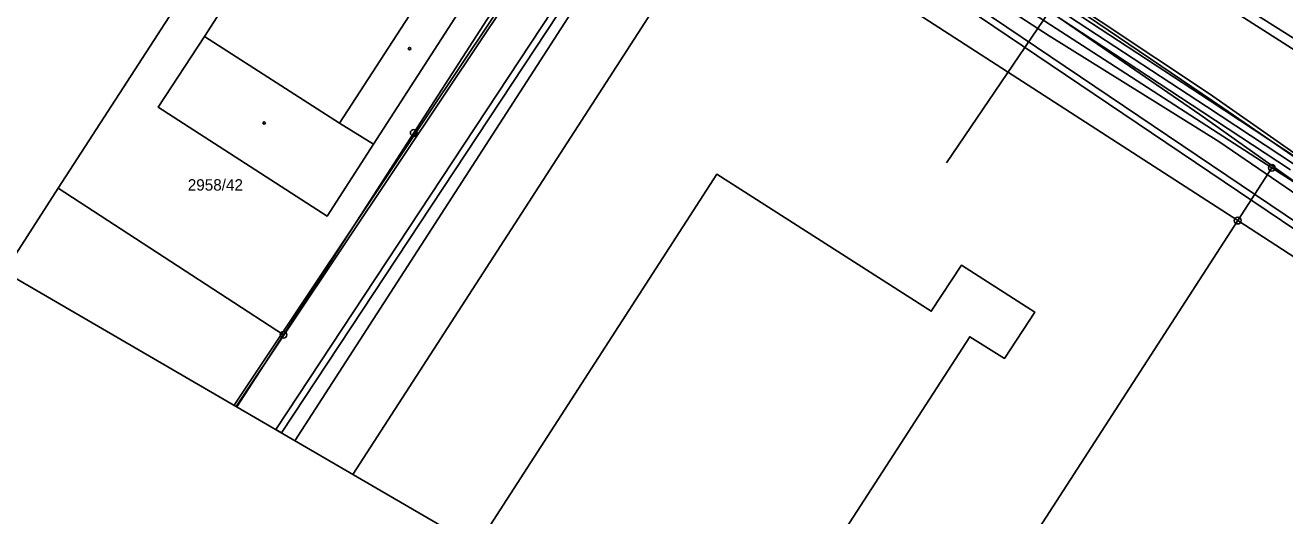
# Model space of a CAD drawing. Extents: x -621168 to -620292, y -1122748 to -1122069.
# Drawn here: x -620762.3 to -620574.7, y -1122596.3 to -1122523.2 of the extents above; entities that cross this region are included whole.
import ezdxf

# ---------------------------------------------------------------- set-up
doc = ezdxf.new("R2010")
doc.units = 0
for name, color, linetype in [('CETIN', 7, 'Continuous'), ('GasNet', 7, 'Continuous'), ('Hranice parcel', 7, 'Continuous'), ('itself', 7, 'Continuous'), ('Parcelní čísla', 7, 'Continuous'), ('Rámečky-tisk', 7, 'Continuous'), ('VAS stoka', 7, 'Continuous'), ('VAS vodovod', 7, 'Continuous'), ('Vnitřní kresba', 7, 'Continuous'), ('Věcná břemena k části', 7, 'Continuous'), ('Značky bodu BP', 7, 'Continuous'), ('Značky budov', 7, 'Continuous')]:
    doc.layers.add(name, color=color, linetype=linetype)

msp = doc.modelspace()

# ---------------------------------------------------------------- linework, layer by layer
at = {"layer": 'CETIN'}
msp.add_lwpolyline([(-620646.43, -1122495.05), (-620612.92, -1122515.84), (-620612.23, -1122516.26), (-620607.1, -1122519.79), (-620583.87, -1122535.51), (-620565.48, -1122548.17), (-620561.56, -1122551.58), (-620557.36, -1122556.05), (-620552.9, -1122562.72), (-620546.13, -1122574.35), (-620544.03, -1122578.53)], dxfattribs=at)
at = {"layer": 'GasNet'}
msp.add_lwpolyline([(-620782.63, -1122409.86), (-620782.01, -1122410.24), (-620780.25, -1122411.07), (-620777.02, -1122412.94), (-620768.84, -1122416.49), (-620765.93, -1122417.88), (-620758.63, -1122422.59), (-620737.62, -1122436.24), (-620727.26, -1122442.97), (-620706.73, -1122456.7), (-620700.22, -1122460.96), (-620682.51, -1122472.52), (-620658.5, -1122488), (-620649.67, -1122493.31), (-620649.45, -1122493.45), (-620648.52, -1122494.04), (-620647.09, -1122494.92), (-620646.9, -1122495.04), (-620639.06, -1122500.54), (-620610.88, -1122519.2), (-620586.31, -1122535.34), (-620573.22, -1122543.96)], dxfattribs=at)
at = {"layer": 'Hranice parcel'}
for p, q in [((-620722.11, -1122585.09), (-620660.74, -1122490.09)), ((-620660.74, -1122490.09), (-620576.58, -1122544.45)), ((-620581.67, -1122552.32), (-620576.58, -1122544.45)), ((-620765.39, -1122559.92), (-620757.37, -1122547.51)), ((-620757.37, -1122547.51), (-620723.81, -1122569.32)), ((-620581.67, -1122552.32), (-620635.41, -1122635.51))]:
    msp.add_line(p, q, dxfattribs=at)
for points in [[(-620557.45, -1122536.96), (-620684.91, -1122455.63), (-620825.92, -1122365.89)], [(-620757.37, -1122547.51), (-620738.01, -1122517.55), (-620702.74, -1122462.95)], [(-620669.14, -1122484.66), (-620704.41, -1122539.26), (-620723.81, -1122569.32)], [(-620702.63, -1122495.93), (-620709.28, -1122506.15), (-620699.07, -1122512.52), (-620694.2, -1122515.81), (-620710.42, -1122540.95), (-620717.32, -1122551.67), (-620742.46, -1122535.43), (-620735.6, -1122524.88), (-620719.36, -1122499.62), (-620712.73, -1122489.39)], [(-620581.67, -1122552.32), (-620657.43, -1122503.38), (-620713.46, -1122590.12)], [(-620576.58, -1122544.45), (-620572.54, -1122547.06), (-620562.8, -1122553.35)], [(-620656.31, -1122623.35), (-620621.58, -1122569.6), (-620616.39, -1122572.84), (-620611.91, -1122565.95), (-620622.82, -1122558.97), (-620627.31, -1122565.82), (-620652.1, -1122549.99), (-620659.27, -1122545.41), (-620695.05, -1122600.83)], [(-620581.67, -1122552.32), (-620562.67, -1122564.59), (-620546.5, -1122612)], [(-620723.81, -1122569.32), (-620730.74, -1122580.07)]]:
    msp.add_lwpolyline(points, dxfattribs=at)
at = {"layer": 'itself'}
msp.add_lwpolyline([(-620570.67, -1122549.95), (-620584.48, -1122540.56), (-620609.76, -1122524.78), (-620613.13, -1122522.62), (-620616.25, -1122520.59), (-620644.13, -1122502.42), (-620648.74, -1122499.33), (-620649.95, -1122498.54), (-620675.91, -1122481.07), (-620699.14, -1122464.9), (-620705.51, -1122460.51), (-620711.67, -1122456.57), (-620715.75, -1122454.11), (-620716.79, -1122453.45), (-620721.67, -1122450.84), (-620745.77, -1122435.49), (-620776.46, -1122415.3)], dxfattribs=at)
at = {"layer": 'Rámečky-tisk'}
msp.add_lwpolyline([(-621018.54, -1122069.17), (-621167.83, -1122325.92), (-620441.66, -1122748.16)], dxfattribs=at)
at = {"layer": 'VAS stoka'}
for points in [[(-620781.72, -1122408.87), (-620776.69, -1122412.14), (-620774.2, -1122412.02), (-620772.21, -1122412.95), (-620766.77, -1122415.95), (-620758.11, -1122421.89), (-620737.16, -1122435.39), (-620726.71, -1122442.22), (-620705.9, -1122455.54), (-620681.71, -1122471.08), (-620665.23, -1122481.83), (-620655.61, -1122488.12), (-620638.12, -1122499.53), (-620609.99, -1122517.38), (-620585.88, -1122533.44), (-620564.23, -1122548.6), (-620546.83, -1122572.05), (-620541.25, -1122582.33), (-620541.87, -1122584.42), (-620543.53, -1122584.85), (-620544.25, -1122585.03)], [(-620730.84, -1122580.01), (-620699.26, -1122532.75), (-620665.23, -1122481.83)]]:
    msp.add_lwpolyline(points, dxfattribs=at)
at = {"layer": 'VAS vodovod'}
msp.add_line((-620609.72, -1122521.13), (-620625.07, -1122543.73), dxfattribs=at)
for points in [[(-620783.05, -1122410.36), (-620779.49, -1122412.44), (-620776.82, -1122413.57), (-620766.15, -1122419), (-620759.23, -1122423.16), (-620738.05, -1122436.88), (-620666.7, -1122483.31), (-620630.69, -1122506.76), (-620611.44, -1122519.95), (-620587.32, -1122536.52), (-620566.14, -1122551.51), (-620558.22, -1122559.71), (-620551.85, -1122569.08), (-620547.83, -1122576.32), (-620546.15, -1122586.98), (-620546.1, -1122587.26)], [(-620666.7, -1122483.31), (-620668.33, -1122485.75), (-620669.96, -1122488.2), (-620702.2, -1122536.43), (-620731.18, -1122579.81)]]:
    msp.add_lwpolyline(points, dxfattribs=at)
at = {"layer": 'Vnitřní kresba'}
for p, q in [((-620570.69, -1122526.84), (-620613.12, -1122500)), ((-620699.07, -1122512.52), (-620715.48, -1122537.82)), ((-620735.6, -1122524.88), (-620715.48, -1122537.82)), ((-620715.48, -1122537.82), (-620710.42, -1122540.95))]:
    msp.add_line(p, q, dxfattribs=at)
at = {"layer": 'Věcná břemena k části'}
msp.add_line((-620724.96, -1122583.43), (-620724.09, -1122583.94), dxfattribs=at)
for points in [[(-620572.64, -1122543.14), (-620585.76, -1122534.5), (-620610.33, -1122518.37), (-620638.51, -1122499.7), (-620681.97, -1122471.68), (-620706.18, -1122455.87), (-620726.71, -1122442.14), (-620758.09, -1122421.75), (-620765.44, -1122417.01)], [(-620766.42, -1122418.75), (-620759.17, -1122423.43), (-620727.81, -1122443.8), (-620707.28, -1122457.53), (-620683.05, -1122473.36), (-620639.61, -1122501.38), (-620611.43, -1122520.03), (-620586.86, -1122536.18), (-620573.8, -1122544.78)], [(-620724.09, -1122583.94), (-620665.73, -1122495.48), (-620663.99, -1122495.13), (-620662.49, -1122492.8), (-620665.58, -1122493.44), (-620724.96, -1122583.43)]]:
    msp.add_lwpolyline(points, dxfattribs=at)
msp.add_lwpolyline([(-620662.49, -1122492.8), (-620663.99, -1122495.13), (-620660.86, -1122494.48), (-620566.61, -1122558.04), (-620561.72, -1122564.46), (-620556.24, -1122574.37), (-620550.21, -1122590.27), (-620556.49, -1122571.86), (-620560.88, -1122563.9), (-620565.91, -1122557.3), (-620661.78, -1122492.65)], close=True, dxfattribs=at)
at = {"layer": 'Značky bodu BP'}
for centre, radius in [((-620704.41, -1122539.26), 0.5), ((-620704.41, -1122539.26), 0.0303), ((-620576.58, -1122544.45), 0.5), ((-620576.58, -1122544.45), 0.0303), ((-620581.67, -1122552.32), 0.5), ((-620581.67, -1122552.32), 0.0303), ((-620723.81, -1122569.32), 0.5), ((-620723.81, -1122569.32), 0.0303)]:
    msp.add_circle(centre, radius, dxfattribs=at)
at = {"layer": 'Značky budov'}
for centre in [(-620705.04, -1122526.7), (-620726.69, -1122537.78)]:
    msp.add_circle(centre, 0.175, dxfattribs=at)

# ---------------------------------------------------------------- texts
at = {"layer": 'Parcelní čísla'}
msp.add_text('2958/42', height=1.7, dxfattribs=at).set_placement((-620738.07, -1122547.85))

doc.saveas('drawing.dxf')
